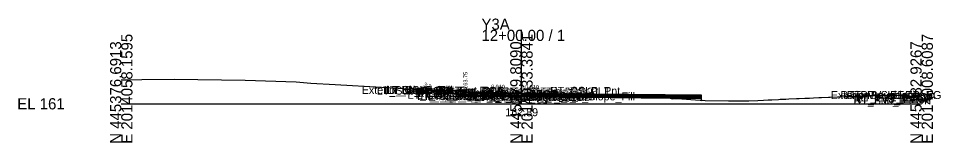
# Model space of a CAD drawing. Extents: x -26 to 205, y -10 to 5029.
# Drawn here: x -25.7 to 204.7, y 3990.3 to 4021.3 of the extents above; entities that cross this region are included whole.
import ezdxf

# ---------------------------------------------------------------- set-up
doc = ezdxf.new("R2010")
doc.units = 0
for name, color, linetype in [('Default', 7, 'Continuous'), ('Exist CMT Pavement', 7, 'Continuous'), ('Exist Cross Section Cell', 7, 'Continuous'), ('Exist XS Center Line Elevation Label', 7, 'Continuous'), ('Exist XS Ground Line', 7, 'Continuous'), ('Prop CMT Conc Surface', 7, 'Continuous'), ('Prop CMT Concrete Structures', 7, 'Continuous'), ('Prop CMT Pvmt Course 1', 7, 'Continuous'), ('Prop CMT Pvmt Course 1 CG', 7, 'Continuous'), ('Prop CMT Pvmt Course 1 Wedge', 7, 'Continuous'), ('Prop CMT Pvmt Course 2', 7, 'Continuous'), ('Prop CMT Pvmt Course 2 Wedge', 7, 'Continuous'), ('Prop CMT Pvmt Course 3', 7, 'Continuous'), ('Prop CMT Pvmt Course 3 Wedge', 7, 'Continuous'), ('Prop CMT Pvmt Surface', 7, 'Continuous'), ('Prop CMT Pvmt Wedge Surface 1', 7, 'Continuous'), ('Prop CMT Pvmt Wedge Surface 2', 7, 'Continuous'), ('Prop CMT Pvmt Wedge Surface 3', 7, 'Continuous'), ('Prop CMT Slope Grass', 7, 'Continuous'), ('Prop CMT Subgrade Earthwork', 7, 'Continuous'), ('Prop XS Earthwork Shape', 7, 'Continuous'), ('Prop XS Hydro Elevations', 7, 'Continuous'), ('Prop XS SE Text', 7, 'Continuous'), ('Prop XS Side Slope Text', 7, 'Continuous'), ('Scratch_Level_0', 7, 'Continuous')]:
    doc.layers.add(name, color=color, linetype=linetype)

msp = doc.modelspace()

# ---------------------------------------------------------------- linework, layer by layer
at = {"layer": 'Exist CMT Pavement'}
msp.add_lwpolyline([(100, 4001.89), (89, 4001.92)], dxfattribs=at)
at = {"layer": 'Exist Cross Section Cell'}
for p, q in [((100, 4000), (100, 4018.49)), ((0, 4000), (100, 4000)), ((100, 4000), (200, 4000))]:
    msp.add_line(p, q, dxfattribs=at)
at = {"layer": 'Exist XS Ground Line'}
msp.add_lwpolyline([(0, 4006.02), (1.96, 4005.99), (5.16, 4006.08), (13.18, 4006.16), (30.92, 4005.93), (43.74, 4005.49), (47.38, 4005.18), (53.42, 4004.84), (65.06, 4004.19), (70.57, 4003.81), (75.52, 4003.51), (85.79, 4002.35), (87.04, 4002.24), (87.45, 4002.17), (88.89, 4001.92), (90.25, 4001.92), (100, 4001.89), (102.15, 4001.88), (109.51, 4001.63), (113.27, 4001.54), (114.54, 4001.55), (115.17, 4002.03), (126.12, 4001.71), (129.04, 4001.63), (129.51, 4001.62), (136.96, 4001.46), (137.68, 4001.23), (138.48, 4001.35), (138.95, 4001.32), (144.68, 4000.87), (145.9, 4000.79), (151.72, 4000.73), (155.59, 4000.7), (156.85, 4000.77), (159.09, 4000.86), (160.51, 4000.93), (161.67, 4000.98), (162.56, 4001.02), (164.26, 4001.11), (164.62, 4001.12), (166.03, 4001.18), (166.84, 4001.21), (168.73, 4001.3), (169.43, 4001.32), (170.79, 4001.38), (172, 4001.43), (173.01, 4001.47), (174.3, 4001.53), (175.01, 4001.55), (176.76, 4001.62), (177.16, 4001.63), (179.01, 4001.7), (179.72, 4001.72), (181.07, 4001.78), (182.3, 4001.83), (183.11, 4001.85), (185.17, 4001.93), (186.32, 4001.96), (187.44, 4001.99), (189.25, 4002.06), (190, 4002.08), (191.22, 4002.12), (192.16, 4002.15), (193.15, 4002.18), (196.65, 4001.97), (200, 4001.78)], dxfattribs=at)
at = {"layer": 'Prop CMT Conc Surface'}
for points in [[(86, 4002.75), (86, 4003.25), (85.5, 4003.25)], [(88, 4002.81), (86, 4002.75)]]:
    msp.add_lwpolyline(points, dxfattribs=at)
at = {"layer": 'Prop CMT Concrete Structures'}
for points in [[(88, 4002.81), (86, 4002.75), (86, 4003.25), (85.5, 4003.25)], [(85.5, 4003.25), (85.5, 4002.26), (88, 4002.23)], [(88, 4002.23), (88, 4002.81)]]:
    msp.add_lwpolyline(points, dxfattribs=at)
at = {"layer": 'Prop CMT Pvmt Course 1'}
for points in [[(100, 4002.69), (88, 4002.81)], [(88, 4002.81), (88, 4002.56)], [(88, 4002.56), (89, 4002.55)], [(89, 4002.55), (89, 4002.68)], [(89, 4002.68), (100, 4002.57)], [(100, 4002.44), (100, 4002.69)], [(100, 4002.69), (144.87, 4002.25)], [(100, 4002.44), (100, 4002.69)], [(100, 4002.57), (100, 4002.44), (100, 4002.44)], [(144.87, 4002), (100, 4002.44)], [(144.87, 4002.25), (144.87, 4002), (144.87, 4002), (144.87, 4002.12)]]:
    msp.add_lwpolyline(points, dxfattribs=at)
at = {"layer": 'Prop CMT Pvmt Course 1 CG'}
for points in [[(88, 4002.23), (85, 4002.26), (84.67, 4001.93)], [(84.67, 4001.93), (88, 4001.9)], [(88, 4001.9), (88, 4002.23)], [(108.34, 4001.69), (105, 4001.73)], [(144.87, 4001.33), (144.87, 4001.66)]]:
    msp.add_lwpolyline(points, dxfattribs=at)
at = {"layer": 'Prop CMT Pvmt Course 1 Wedge'}
msp.add_lwpolyline([(100, 4002.57), (89, 4002.68)], dxfattribs=at)
at = {"layer": 'Prop CMT Pvmt Course 2'}
for points in [[(89, 4002.55), (88, 4002.56)], [(88, 4002.56), (88, 4002.23)], [(89, 4002.22), (89, 4002.55)], [(100, 4002.11), (100, 4002.44)], [(100, 4002.44), (144.87, 4002)], [(88, 4002.23), (89, 4002.22)], [(144.87, 4001.66), (100, 4002.11)], [(144.87, 4001.66), (144.87, 4001.66), (144.87, 4002), (144.87, 4002)], [(144.87, 4002), (144.87, 4001.66)]]:
    msp.add_lwpolyline(points, dxfattribs=at)
at = {"layer": 'Prop CMT Pvmt Course 2 Wedge'}
for points in [[(100, 4002.44), (89, 4002.55)], [(144.87, 4002), (105, 4002.39)]]:
    msp.add_lwpolyline(points, dxfattribs=at)
at = {"layer": 'Prop CMT Pvmt Course 3'}
for points in [[(89, 4002.22), (88, 4002.23)], [(88, 4002.23), (88, 4001.9)], [(88, 4001.9), (89, 4001.89)], [(89, 4001.89), (89, 4002.22)], [(100, 4002.11), (144.87, 4001.66)], [(100, 4001.78), (100, 4002.11)], [(144.87, 4001.33), (100, 4001.78)], [(144.87, 4001.66), (144.87, 4001.66), (144.87, 4001.33), (144.87, 4001.33)], [(144.87, 4001.33), (144.87, 4001.66)]]:
    msp.add_lwpolyline(points, dxfattribs=at)
at = {"layer": 'Prop CMT Pvmt Course 3 Wedge'}
for points in [[(100, 4002.11), (89, 4002.22)], [(144.87, 4001.66), (105, 4002.06)]]:
    msp.add_lwpolyline(points, dxfattribs=at)
at = {"layer": 'Prop CMT Pvmt Surface'}
for points in [[(100, 4002.69), (88, 4002.81)], [(100, 4002.69), (144.87, 4002.25)]]:
    msp.add_lwpolyline(points, dxfattribs=at)
at = {"layer": 'Prop CMT Pvmt Wedge Surface 1'}
for points in [[(88, 4002.56), (88, 4002.81)], [(89, 4002.55), (88, 4002.56)], [(100, 4002.57), (89, 4002.68)], [(89, 4002.68), (89, 4002.55)], [(100, 4002.69), (100, 4002.44)], [(100, 4002.44), (144.87, 4002)], [(144.87, 4002), (144.87, 4002.25)], [(144.87, 4002.12), (144.87, 4002), (144.87, 4002)]]:
    msp.add_lwpolyline(points, dxfattribs=at)
at = {"layer": 'Prop CMT Pvmt Wedge Surface 2'}
for points in [[(88, 4002.56), (88, 4002.81)], [(100, 4002.44), (88, 4002.56)], [(100, 4002.69), (100, 4002.44)], [(100, 4002.44), (144.87, 4002)], [(144.87, 4002), (105, 4002.39)], [(144.87, 4002), (144.87, 4002.25)]]:
    msp.add_lwpolyline(points, dxfattribs=at)
at = {"layer": 'Prop CMT Pvmt Wedge Surface 3'}
for points in [[(88, 4002.23), (88, 4002.81)], [(100, 4002.69), (100, 4002.11)], [(100, 4002.11), (88, 4002.23)], [(100, 4002.11), (144.87, 4001.66)], [(144.87, 4001.66), (105, 4002.06)], [(144.87, 4001.66), (144.87, 4002.25)]]:
    msp.add_lwpolyline(points, dxfattribs=at)
at = {"layer": 'Prop CMT Slope Grass'}
msp.add_lwpolyline([(85.5, 4003.25), (76, 4003.44), (75.95, 4003.46)], dxfattribs=at)
msp.add_lwpolyline([(85.5, 4003.25), (76, 4003.44), (75.95, 4003.46)], dxfattribs=at)
at = {"layer": 'Prop CMT Subgrade Earthwork'}
for p, q in [((100, 4001.78), (100, 4001.89)), ((144.87, 4002.25), (144.87, 4001.33)), ((144.87, 4001.33), (144.99, 4000.85))]:
    msp.add_line(p, q, dxfattribs=at)
for points in [[(88, 4001.9), (84.67, 4001.93), (83.3, 4003.3)], [(89, 4001.89), (88, 4001.9)], [(89, 4001.89), (89, 4001.92)], [(100, 4001.78), (144.87, 4001.33)], [(144.87, 4001.33), (144.87, 4001.33)]]:
    msp.add_lwpolyline(points, dxfattribs=at)
at = {"layer": 'Prop XS Earthwork Shape'}
for points in [[(76.12, 4003.44), (76, 4003.44), (75.95, 4003.46)], [(83.3, 4003.3), (76.12, 4003.44), (84.06, 4002.55)], [(84.67, 4001.93), (84.06, 4002.55), (85.5, 4002.38), (85.5, 4002.26), (87.06, 4002.24), (87.45, 4002.17), (88.89, 4001.92), (89, 4001.92), (89, 4001.89), (88, 4001.9)], [(85.5, 4002.38), (85.79, 4002.35), (87.04, 4002.24), (87.06, 4002.24), (85.5, 4002.26)], [(102.15, 4001.88), (107.38, 4001.7), (100, 4001.78), (100, 4001.89)], [(109.51, 4001.63), (113.27, 4001.54), (114.54, 4001.55), (114.64, 4001.63), (107.38, 4001.7)], [(126.12, 4001.71), (129.04, 4001.63), (129.51, 4001.62), (136.96, 4001.46), (137.13, 4001.41), (114.64, 4001.63), (115.17, 4002.03)], [(137.68, 4001.23), (138.48, 4001.35), (138.95, 4001.32), (144.68, 4000.87), (144.99, 4000.85), (144.87, 4001.33), (137.13, 4001.41)]]:
    msp.add_lwpolyline(points, close=True, dxfattribs=at)

# ---------------------------------------------------------------- texts
at = {"layer": 'Default'}
msp.add_text('-', height=0.0001, dxfattribs=at).set_placement((0, 4000))
at = {"layer": 'Exist Cross Section Cell'}
for s, p in [('Y3A', (90, 4018.49)), ('12+00.00 / 1', (90, 4015.69)), ('EL 161', (-26, 3998.6))]:
    msp.add_text(s, height=2.8, dxfattribs=at).set_placement(p)
for s, p in [('E 2014058.1595', (2.8, 3990)), ('E 2014033.3841', (102.8, 3990)), ('E 2014008.6087', (202.8, 3990)), ('N 445376.6913', (0, 3990)), ('N 445279.8090', (100, 3990)), ('N 445182.9267', (200, 3990))]:
    msp.add_text(s, height=2.8, rotation=90, dxfattribs=at).set_placement(p)
at = {"layer": 'Exist XS Center Line Elevation Label'}
msp.add_text('162.89', height=2, dxfattribs=at).set_placement((95.97, 3996.89))
at = {"layer": 'Prop XS Hydro Elevations'}
msp.add_text('163.75', height=1, rotation=90, dxfattribs=at).set_placement((86.5, 4003.75))
msp.add_text('163.75', height=1, rotation=90, dxfattribs=at).set_placement((86.5, 4003.75))
at = {"layer": 'Prop XS SE Text'}
for p in [(92.38, 4003.77), (92.38, 4003.77), (100.88, 4003.69), (100.88, 4003.69)]:
    msp.add_text('0.010', height=1, rotation=359.4271, dxfattribs=at).set_placement(p)
at = {"layer": 'Prop XS Side Slope Text'}
msp.add_text('3:1', height=1, rotation=341.5652, dxfattribs=at).set_placement((75.46, 4004.42))
msp.add_text('3:1', height=1, rotation=341.5652, dxfattribs=at).set_placement((75.46, 4004.42))
msp.add_text('3:1', height=1, rotation=341.5652, dxfattribs=at).set_placement((75.46, 4004.42))
msp.add_text('3:1', height=1, rotation=341.5652, dxfattribs=at).set_placement((75.46, 4004.42))
at = {"layer": 'Scratch_Level_0'}
for s, p in [('Exterior Boundary', (60.09, 4002.46)), ('LT_Sub_Trench_Out_DLT', (63.87, 4002.3)), ('LT_Slope_Cut', (65.58, 4002.46)), ('LT_CSLP_Pnt', (66.17, 4002.44)), ('LT_Slope_Fill', (66.47, 4002.46)), ('LT_CG1_Shelf_Out', (71.55, 4001.26)), ('LT_CG_Top_Face', (73.26, 4002.25)), ('LT_CG_Top_BOC', (73.78, 4002.25)), ('LT_CG_Bot_BOC', (73.81, 4001.26)), ('LT_PV_Sub_Tie_Out', (73.96, 4000.92)), ('LT_CG_Top_Gut', (74.24, 4001.75)), ('LT_Sub_OEOP', (74.78, 4000.93)), ('LT_PV_OEEOP_EG', (76.54, 4000.92)), ('LT_CG_Bot_IE', (77.91, 4001.23)), ('LT_Sub_OEOT', (78.08, 4000.9)), ('LT_PV2_OEOT', (78.17, 4001.56)), ('LT_PV3_OEOT', (78.17, 4001.23)), ('LT_Sub_OEEOP', (78.21, 4000.89)), ('LT_PV2_OEEOP', (78.31, 4001.55)), ('LT_PV3_OEEOP', (78.31, 4001.22)), ('LT_PV1_OEOT', (78.74, 4001.81)), ('LT_PV1_OEEOP', (78.87, 4001.68)), ('LT_PV_IEEOP_EG', (88.19, 4000.89)), ('RT_PV_Sub_Tie_Out', (89.88, 4000.78)), ('LT_PV2_IEEOP', (89.95, 4001.44)), ('LT_PV3_IEEOP', (89.95, 4001.11)), ('RT_Sub_Trench_Out_DLT', (90.25, 4002.09)), ('LT_PV1_IEEOP', (90.52, 4001.57)), ('RT_PV_OEEOP_EG', (92.5, 4000.78)), ('Sub_PGL', (93.81, 4000.78)), ('PV2_PGL', (93.91, 4001.44)), ('PV3_PGL', (93.91, 4001.11)), ('RT_Sub_OEEOP', (94.17, 4000.73)), ('RT_CG_Top_Face', (94.21, 4002.04)), ('RT_PV2_OEEOP', (94.26, 4001.39)), ('RT_PV3_OEEOP', (94.26, 4001.06)), ('PV1_PGL', (94.47, 4001.69)), ('RT_CG1_Shelf_Out', (94.5, 4001.03)), ('RT_PV1_OEEOP', (94.83, 4001.52)), ('RT_CG_Bot_IE', (94.87, 4001.06)), ('RT_Sub_OEOT', (95.03, 4000.73)), ('RT_PV2_OEOT', (95.13, 4001.39)), ('RT_PV3_OEOT', (95.13, 4001.06)), ('RT_CG_Top_Gut', (95.19, 4001.54)), ('RT_PV1_OEOT', (95.69, 4001.64)), ('RT_CG_Top_BOC', (95.74, 4002.04)), ('RT_CG_Bot_BOC', (95.77, 4001.04)), ('RT_Sub_OEOP', (98.4, 4000.69)), ('RT_CSLP_Pnt', (107.13, 4002.23)), ('RT_Slope_Fill', (111.61, 4000.86)), ('Exterior Boundary', (177.3, 4001.18)), ('RT_PV_Sub_Tie_In', (179.68, 4001.18)), ('RT_PV_IEEOP_EG', (181.29, 4001.18)), ('RT_PV2_IEEOP', (183.05, 4000.51)), ('RT_PV1_IEEOP', (183.62, 4000.64)), ('RT_Sub_IEEOP', (182.96, 3999.85)), ('RT_PV3_IEEOP', (183.05, 4000.18))]:
    msp.add_text(s, height=2, dxfattribs=at).set_placement(p)

doc.saveas('drawing.dxf')
